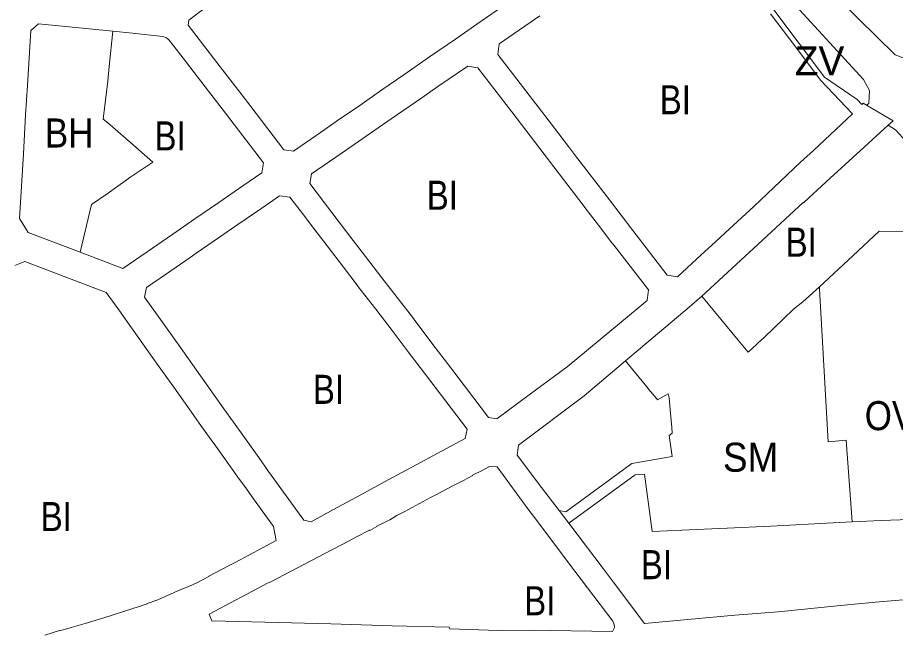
# Model space of a CAD drawing. Extents: x -650451 to -642268, y -1075216 to -1066610.
# Drawn here: x -646618.6 to -646255.8, y -1070923.2 to -1070669.1 of the extents above; entities that cross this region are included whole.
import ezdxf

# ---------------------------------------------------------------- set-up
doc = ezdxf.new("R2010")
doc.units = 0
doc.header["$LTSCALE"] = 4.8
for name, color, linetype, lineweight in [('1', 7, 'Continuous', 13), ('11', 7, 'Continuous', 13), ('15', 7, 'Continuous', 13), ('18', 7, 'Continuous', 13), ('2', 7, 'Continuous', 13), ('24', 7, 'Continuous', 13), ('40', 7, 'Continuous', 13)]:
    doc.layers.add(name, color=color, linetype=linetype, lineweight=lineweight)
doc.layers.add('62', color=7, linetype='Continuous')

msp = doc.modelspace()

# ---------------------------------------------------------------- linework, layer by layer
at = {"layer": '1'}
for points in [[(-646592.74, -1070766.01), (-646614.24, -1070757.93), (-646617.81, -1070752.22), (-646616.16, -1070725.38), (-646615.28, -1070709.36), (-646614.51, -1070697.27), (-646613.1, -1070674.47), (-646609.86, -1070671.71), (-646579.22, -1070674.79)], [(-646579.22, -1070674.79), (-646580.7, -1070689.38), (-646581.31, -1070695.46), (-646583.19, -1070711.07), (-646581.26, -1070712.65), (-646571.85, -1070720.76), (-646562.69, -1070728.82), (-646571.8, -1070734.95), (-646581.48, -1070741.91), (-646588, -1070746.38), (-646592.74, -1070766.01)]]:
    msp.add_lwpolyline(points, dxfattribs=at)
at = {"layer": '11'}
for points in [[(-646247.88, -1070687.56), (-646255.97, -1070684.58), (-646294.19, -1070646.82), (-646301.17, -1070639.92), (-646311.36, -1070629.16)], [(-646287.24, -1070780.35), (-646273.46, -1070767.61), (-646262.47, -1070757.43), (-646243.81, -1070757.55), (-646239.14, -1070757.8), (-646220.63, -1070758.81), (-646220.91, -1070795.61), (-646212.22, -1070805.08), (-646211.32, -1070874.4), (-646242.24, -1070875.39), (-646242.15, -1070876.28), (-646261.64, -1070876.91), (-646273.62, -1070877.57)], [(-646273.62, -1070877.57), (-646276.19, -1070843.8), (-646283.65, -1070844.41), (-646287.18, -1070781.33), (-646287.24, -1070780.35)]]:
    msp.add_lwpolyline(points, dxfattribs=at)
at = {"layer": '15'}
for points in [[(-646333.79, -1070624.42), (-646336.15, -1070622.85), (-646338.7, -1070622.45), (-646285.17, -1070693.77), (-646271.56, -1070702.94), (-646269.72, -1070705.08), (-646269.19, -1070704.55), (-646267.8, -1070705.35)], [(-646521.27, -1070649.9), (-646547.81, -1070670.15), (-646548.1, -1070672.21), (-646536.18, -1070687.66), (-646524.4, -1070703.04), (-646508.56, -1070723.74), (-646504.5, -1070724.28), (-646491.62, -1070715.45), (-646486.3, -1070711.74), (-646477.13, -1070705.41), (-646468, -1070699.01), (-646459.02, -1070692.78), (-646448.34, -1070685.41), (-646437.61, -1070678.02), (-646428.78, -1070671.9), (-646418.14, -1070664.55)], [(-646402.77, -1070668.45), (-646419.56, -1070680.05), (-646420.13, -1070684.38), (-646400.7, -1070709.54), (-646390.88, -1070722.36), (-646388.36, -1070725.66), (-646373.97, -1070744.49), (-646364.37, -1070757.12), (-646350.16, -1070775.6), (-646345.85, -1070776.25), (-646336.08, -1070767.24), (-646330.21, -1070761.82), (-646324.43, -1070756.49), (-646314.34, -1070747.19), (-646294.97, -1070728.93), (-646289.73, -1070724), (-646273.5, -1070708.86), (-646286.71, -1070695.05), (-646297.03, -1070681.4), (-646307.43, -1070667.64)], [(-646579.22, -1070674.79), (-646609.86, -1070671.71), (-646613.1, -1070674.47), (-646614.51, -1070697.27), (-646615.28, -1070709.36), (-646616.16, -1070725.38), (-646617.81, -1070752.22), (-646614.24, -1070757.93), (-646592.74, -1070766.01)], [(-646592.74, -1070766.01), (-646575.04, -1070772.84), (-646565.04, -1070765.98), (-646554.42, -1070758.64), (-646545.27, -1070752.32), (-646535.35, -1070745.54), (-646525.54, -1070738.72), (-646517.65, -1070733.33), (-646516.96, -1070729.11), (-646532.58, -1070708.64), (-646541.02, -1070697.81), (-646549.18, -1070687.18), (-646555.94, -1070678.43), (-646556.99, -1070677.45), (-646558.56, -1070676.91), (-646571.12, -1070675.62), (-646579.22, -1070674.79)], [(-646267.8, -1070705.35), (-646258.4, -1070710.8), (-646256.75, -1070711.76), (-646258.82, -1070713.65)], [(-646258.82, -1070713.65), (-646268.69, -1070722.68), (-646282.71, -1070735.5), (-646291.55, -1070743.61), (-646293.76, -1070745.64), (-646293.88, -1070745.53), (-646314.42, -1070764.61), (-646335.79, -1070784.31)], [(-646607.28, -1070924.28), (-646601.24, -1070922.45), (-646601.21, -1070922.55), (-646597.21, -1070921.5), (-646597.23, -1070921.42), (-646596.48, -1070921.2), (-646590.69, -1070919.54), (-646582.94, -1070917.19), (-646570.93, -1070913.38), (-646568.79, -1070912.59), (-646568.77, -1070912.65), (-646565.04, -1070911.35), (-646565.07, -1070911.27), (-646560.62, -1070909.67), (-646551.07, -1070905.53), (-646547.56, -1070904.07), (-646544.49, -1070902.67), (-646539.51, -1070900.14), (-646539.58, -1070899.99), (-646531.36, -1070895.72), (-646528.66, -1070894.25), (-646511.73, -1070885.17), (-646512.86, -1070879.39), (-646517.52, -1070872.91), (-646521.79, -1070866.98), (-646523.99, -1070863.92), (-646527.51, -1070859.02), (-646536.69, -1070846.22), (-646538.56, -1070843.6), (-646543.47, -1070836.73), (-646545.39, -1070834.04), (-646547.66, -1070830.82), (-646554.04, -1070821.8), (-646560.47, -1070812.84), (-646562.8, -1070809.59), (-646566.12, -1070804.92), (-646571.44, -1070797.41), (-646576.79, -1070789.95), (-646581.91, -1070782.8), (-646615.61, -1070769.98), (-646619.65, -1070771.61)], [(-646335.79, -1070784.31), (-646341.08, -1070788.84), (-646361.19, -1070805.8), (-646367.37, -1070811.01)], [(-646367.37, -1070811.01), (-646384.39, -1070825.4), (-646411.54, -1070845.82), (-646412.09, -1070850.01), (-646402.03, -1070863.32), (-646394.8, -1070872.88), (-646390.83, -1070878.08)], [(-646390.83, -1070878.08), (-646376.59, -1070896.75), (-646372.4, -1070902.33), (-646359.51, -1070919.54), (-646340.14, -1070917.72), (-646322.16, -1070916.14), (-646304.25, -1070914.63), (-646278.52, -1070912.13), (-646262.54, -1070910.59), (-646242.55, -1070908.96), (-646242.5, -1070912.81), (-646183.68, -1070907.2), (-646147.38, -1070905.61)]]:
    msp.add_lwpolyline(points, dxfattribs=at)
for points in [[(-646420.52, -1070835.01), (-646407.1, -1070825.05), (-646391.43, -1070813.52), (-646369.02, -1070794.9), (-646358.37, -1070786.01), (-646357.9, -1070781.68), (-646372.03, -1070763.39), (-646372.96, -1070762.19), (-646378.56, -1070754.88), (-646384.1, -1070747.66), (-646385.28, -1070746.12), (-646392.96, -1070736.08), (-646400.95, -1070725.63), (-646414.28, -1070708.14), (-646428.4, -1070689.86), (-646432.55, -1070689.24), (-646444.9, -1070697.64), (-646451.53, -1070702.27), (-646464.15, -1070710.94), (-646466.04, -1070712.24), (-646484.43, -1070725.08), (-646497.08, -1070733.65), (-646497.86, -1070737.68), (-646482.67, -1070757.72), (-646474.73, -1070767.91), (-646468.01, -1070776.68), (-646455.41, -1070792.92), (-646454.66, -1070793.88), (-646447.34, -1070803.67), (-646439.48, -1070813.93), (-646423.95, -1070834.45)], [(-646497.22, -1070877.56), (-646488.07, -1070872.46), (-646476.73, -1070866.39), (-646465.37, -1070860.15), (-646453.9, -1070853.97), (-646445.11, -1070849.23), (-646433.61, -1070843.06), (-646432.82, -1070839.18), (-646450.45, -1070816.03), (-646457.11, -1070807.28), (-646463.79, -1070798.5), (-646470.55, -1070789.67), (-646476.6, -1070781.92), (-646477.22, -1070781.13), (-646478.27, -1070779.74), (-646483.9, -1070772.33), (-646490.62, -1070763.47), (-646497.57, -1070754.46), (-646499.92, -1070751.4), (-646506.12, -1070743.36), (-646510.3, -1070742.84), (-646517.66, -1070747.84), (-646527.54, -1070754.62), (-646530.2, -1070756.46), (-646537.36, -1070761.39), (-646544.71, -1070766.53), (-646547.25, -1070768.31), (-646557.07, -1070775.09), (-646565.27, -1070780.67), (-646566.15, -1070784.66), (-646559.52, -1070793.94), (-646551.97, -1070804.52), (-646533.33, -1070830.75), (-646529.38, -1070836.27), (-646524.12, -1070843.61), (-646518.91, -1070850.95), (-646514.84, -1070856.69), (-646500.27, -1070876.87)], [(-646372.66, -1070922.87), (-646371.95, -1070921.1), (-646372, -1070919.88), (-646372.62, -1070918.59), (-646390.97, -1070894.38), (-646404.46, -1070876.47), (-646407.32, -1070872.68), (-646420.35, -1070854.79), (-646423.59, -1070854.62), (-646426.3, -1070856.12), (-646430.52, -1070858.22), (-646430.43, -1070858.37), (-646434.59, -1070860.54), (-646434.62, -1070860.5), (-646439.32, -1070862.86), (-646439.27, -1070862.95), (-646445.22, -1070866.14), (-646445.24, -1070866.09), (-646447.87, -1070867.49), (-646458.56, -1070873.21), (-646461.82, -1070874.95), (-646464.79, -1070876.65), (-646470.13, -1070879.34), (-646470.06, -1070879.48), (-646473.04, -1070881.08), (-646473.12, -1070880.93), (-646478.55, -1070883.72), (-646481.78, -1070885.45), (-646484.71, -1070886.98), (-646491.59, -1070890.64), (-646513.9, -1070902.3), (-646514.97, -1070902.75), (-646539.4, -1070915.68), (-646538.3, -1070918.46), (-646505.36, -1070919.27), (-646489.12, -1070919.72), (-646463.78, -1070920.43), (-646440.21, -1070921.07), (-646439.9, -1070921.7), (-646419.98, -1070922.36), (-646406.75, -1070922.27)]]:
    msp.add_lwpolyline(points, close=True, dxfattribs=at)
at = {"layer": '18'}
for points in [[(-646335.79, -1070784.31), (-646320.76, -1070802.46), (-646316.66, -1070807.4), (-646313.05, -1070804.07), (-646312.33, -1070803.39), (-646310.07, -1070801.3), (-646297.92, -1070789.63), (-646294.02, -1070786.62), (-646287.24, -1070780.35)], [(-646287.24, -1070780.35), (-646287.18, -1070781.33), (-646283.65, -1070844.41), (-646276.19, -1070843.8), (-646273.62, -1070877.57)], [(-646367.37, -1070811.01), (-646361.19, -1070805.8), (-646341.08, -1070788.84), (-646335.79, -1070784.31)], [(-646394.8, -1070872.88), (-646391.94, -1070873.33), (-646364.69, -1070853.45), (-646348.09, -1070850.57), (-646349.3, -1070841.85), (-646348.01, -1070840.87), (-646348.18, -1070838.52), (-646348.74, -1070832.73), (-646349.36, -1070826.25), (-646349.67, -1070824.67), (-646354.07, -1070827.06), (-646354.38, -1070826.7), (-646357.65, -1070822.88), (-646357.93, -1070822.48), (-646367.37, -1070811.01)], [(-646273.62, -1070877.57), (-646281.55, -1070877.98), (-646307.29, -1070879.32), (-646325.34, -1070880.17), (-646344.2, -1070881.01), (-646344.47, -1070881.02), (-646350.1, -1070881.27), (-646356.37, -1070881.56), (-646359.49, -1070857.84), (-646363.38, -1070858.06), (-646390.83, -1070878.08), (-646394.8, -1070872.88)]]:
    msp.add_lwpolyline(points, dxfattribs=at)
at = {"layer": '2'}
for points in [[(-646418.14, -1070664.55), (-646428.78, -1070671.9), (-646437.61, -1070678.02), (-646448.34, -1070685.41), (-646459.02, -1070692.78), (-646468, -1070699.01), (-646477.13, -1070705.41), (-646486.3, -1070711.74), (-646491.62, -1070715.45), (-646504.5, -1070724.28), (-646508.56, -1070723.74), (-646524.4, -1070703.04), (-646536.18, -1070687.66), (-646548.1, -1070672.21), (-646547.81, -1070670.15), (-646521.27, -1070649.9)], [(-646307.43, -1070667.64), (-646297.03, -1070681.4), (-646286.71, -1070695.05), (-646273.5, -1070708.86), (-646289.73, -1070724), (-646294.97, -1070728.93), (-646314.34, -1070747.19), (-646324.43, -1070756.49), (-646330.21, -1070761.82), (-646336.08, -1070767.24), (-646345.85, -1070776.25), (-646350.16, -1070775.6), (-646364.37, -1070757.12), (-646373.97, -1070744.49), (-646388.36, -1070725.66), (-646390.88, -1070722.36), (-646400.7, -1070709.54), (-646420.13, -1070684.38), (-646419.56, -1070680.05), (-646402.77, -1070668.45)], [(-646592.74, -1070766.01), (-646588, -1070746.38), (-646581.48, -1070741.91), (-646571.8, -1070734.95), (-646562.69, -1070728.82), (-646571.85, -1070720.76), (-646581.26, -1070712.65), (-646583.19, -1070711.07), (-646581.31, -1070695.46), (-646580.7, -1070689.38), (-646579.22, -1070674.79)], [(-646579.22, -1070674.79), (-646571.12, -1070675.62), (-646558.56, -1070676.91), (-646556.99, -1070677.45), (-646555.94, -1070678.43), (-646549.18, -1070687.18), (-646541.02, -1070697.81), (-646532.58, -1070708.64), (-646516.96, -1070729.11), (-646517.65, -1070733.33), (-646525.54, -1070738.72), (-646535.35, -1070745.54), (-646545.27, -1070752.32), (-646554.42, -1070758.64), (-646565.04, -1070765.98), (-646575.04, -1070772.84), (-646592.74, -1070766.01)], [(-646335.79, -1070784.31), (-646314.42, -1070764.61), (-646293.88, -1070745.53), (-646293.76, -1070745.64), (-646291.55, -1070743.61), (-646282.71, -1070735.5), (-646268.69, -1070722.68), (-646258.82, -1070713.65), (-646255.82, -1070715.54), (-646251.18, -1070720.48), (-646244.1, -1070726.79), (-646242.06, -1070728.61), (-646239.25, -1070731.88)], [(-646273.62, -1070877.57), (-646261.64, -1070876.91), (-646242.15, -1070876.28), (-646242.24, -1070875.39), (-646211.32, -1070874.4), (-646212.22, -1070805.08), (-646220.91, -1070795.61), (-646220.63, -1070758.81), (-646239.14, -1070757.8), (-646243.81, -1070757.55), (-646262.47, -1070757.43), (-646273.46, -1070767.61), (-646287.24, -1070780.35)], [(-646619.65, -1070771.61), (-646615.61, -1070769.98), (-646581.91, -1070782.8), (-646576.79, -1070789.95), (-646571.44, -1070797.41), (-646566.12, -1070804.92), (-646562.8, -1070809.59), (-646560.47, -1070812.84), (-646554.04, -1070821.8), (-646547.66, -1070830.82), (-646545.39, -1070834.04), (-646543.47, -1070836.73), (-646538.56, -1070843.6), (-646536.69, -1070846.22), (-646527.51, -1070859.02), (-646523.99, -1070863.92), (-646521.79, -1070866.98), (-646517.52, -1070872.91), (-646512.86, -1070879.39), (-646511.73, -1070885.17), (-646528.66, -1070894.25), (-646531.36, -1070895.72), (-646539.58, -1070899.99), (-646539.51, -1070900.14), (-646544.49, -1070902.67), (-646547.56, -1070904.07), (-646551.07, -1070905.53), (-646560.62, -1070909.67), (-646565.07, -1070911.27), (-646565.04, -1070911.35), (-646568.77, -1070912.65), (-646568.79, -1070912.59), (-646570.93, -1070913.38), (-646582.94, -1070917.19), (-646590.69, -1070919.54), (-646596.48, -1070921.2), (-646597.23, -1070921.42), (-646597.21, -1070921.5), (-646601.21, -1070922.55), (-646601.24, -1070922.45), (-646607.28, -1070924.28)], [(-646287.24, -1070780.35), (-646294.02, -1070786.62), (-646297.92, -1070789.63), (-646310.07, -1070801.3), (-646312.33, -1070803.39), (-646313.05, -1070804.07), (-646316.66, -1070807.4), (-646320.76, -1070802.46), (-646335.79, -1070784.31)], [(-646394.8, -1070872.88), (-646402.03, -1070863.32), (-646412.09, -1070850.01), (-646411.54, -1070845.82), (-646384.39, -1070825.4), (-646367.37, -1070811.01)], [(-646367.37, -1070811.01), (-646357.93, -1070822.48), (-646357.65, -1070822.88), (-646354.38, -1070826.7), (-646354.07, -1070827.06), (-646349.67, -1070824.67), (-646349.36, -1070826.25), (-646348.74, -1070832.73), (-646348.18, -1070838.52), (-646348.01, -1070840.87), (-646349.3, -1070841.85), (-646348.09, -1070850.57), (-646364.69, -1070853.45), (-646391.94, -1070873.33), (-646394.8, -1070872.88)], [(-646390.83, -1070878.08), (-646363.38, -1070858.06), (-646359.49, -1070857.84), (-646356.37, -1070881.56), (-646350.1, -1070881.27), (-646344.47, -1070881.02), (-646344.2, -1070881.01), (-646325.34, -1070880.17), (-646307.29, -1070879.32), (-646281.55, -1070877.98), (-646273.62, -1070877.57)], [(-646147.38, -1070905.61), (-646183.68, -1070907.2), (-646242.5, -1070912.81), (-646242.55, -1070908.96), (-646262.54, -1070910.59), (-646278.52, -1070912.13), (-646304.25, -1070914.63), (-646322.16, -1070916.14), (-646340.14, -1070917.72), (-646359.51, -1070919.54), (-646372.4, -1070902.33), (-646376.59, -1070896.75), (-646390.83, -1070878.08)]]:
    msp.add_lwpolyline(points, dxfattribs=at)
for points in [[(-646420.52, -1070835.01), (-646423.95, -1070834.45), (-646439.48, -1070813.93), (-646447.34, -1070803.67), (-646454.66, -1070793.88), (-646455.41, -1070792.92), (-646468.01, -1070776.68), (-646474.73, -1070767.91), (-646482.67, -1070757.72), (-646497.86, -1070737.68), (-646497.08, -1070733.65), (-646484.43, -1070725.08), (-646466.04, -1070712.24), (-646464.15, -1070710.94), (-646451.53, -1070702.27), (-646444.9, -1070697.64), (-646432.55, -1070689.24), (-646428.4, -1070689.86), (-646414.28, -1070708.14), (-646400.95, -1070725.63), (-646392.96, -1070736.08), (-646385.28, -1070746.12), (-646384.1, -1070747.66), (-646378.56, -1070754.88), (-646372.96, -1070762.19), (-646372.03, -1070763.39), (-646357.9, -1070781.68), (-646358.37, -1070786.01), (-646369.02, -1070794.9), (-646391.43, -1070813.52), (-646407.1, -1070825.05)], [(-646497.22, -1070877.56), (-646500.27, -1070876.87), (-646514.84, -1070856.69), (-646518.91, -1070850.95), (-646524.12, -1070843.61), (-646529.38, -1070836.27), (-646533.33, -1070830.75), (-646551.97, -1070804.52), (-646559.52, -1070793.94), (-646566.15, -1070784.66), (-646565.27, -1070780.67), (-646557.07, -1070775.09), (-646547.25, -1070768.31), (-646544.71, -1070766.53), (-646537.36, -1070761.39), (-646530.2, -1070756.46), (-646527.54, -1070754.62), (-646517.66, -1070747.84), (-646510.3, -1070742.84), (-646506.12, -1070743.36), (-646499.92, -1070751.4), (-646497.57, -1070754.46), (-646490.62, -1070763.47), (-646483.9, -1070772.33), (-646478.27, -1070779.74), (-646477.22, -1070781.13), (-646476.6, -1070781.92), (-646470.55, -1070789.67), (-646463.79, -1070798.5), (-646457.11, -1070807.28), (-646450.45, -1070816.03), (-646432.82, -1070839.18), (-646433.61, -1070843.06), (-646445.11, -1070849.23), (-646453.9, -1070853.97), (-646465.37, -1070860.15), (-646476.73, -1070866.39), (-646488.07, -1070872.46)], [(-646372.66, -1070922.87), (-646406.75, -1070922.27), (-646419.98, -1070922.36), (-646439.9, -1070921.7), (-646440.21, -1070921.07), (-646463.78, -1070920.43), (-646489.12, -1070919.72), (-646505.36, -1070919.27), (-646538.3, -1070918.46), (-646539.4, -1070915.68), (-646514.97, -1070902.75), (-646513.9, -1070902.3), (-646491.59, -1070890.64), (-646484.71, -1070886.98), (-646481.78, -1070885.45), (-646478.55, -1070883.72), (-646473.12, -1070880.93), (-646473.04, -1070881.08), (-646470.06, -1070879.48), (-646470.13, -1070879.34), (-646464.79, -1070876.65), (-646461.82, -1070874.95), (-646458.56, -1070873.21), (-646447.87, -1070867.49), (-646445.24, -1070866.09), (-646445.22, -1070866.14), (-646439.27, -1070862.95), (-646439.32, -1070862.86), (-646434.62, -1070860.5), (-646434.59, -1070860.54), (-646430.43, -1070858.37), (-646430.52, -1070858.22), (-646426.3, -1070856.12), (-646423.59, -1070854.62), (-646420.35, -1070854.79), (-646407.32, -1070872.68), (-646404.46, -1070876.47), (-646390.97, -1070894.38), (-646372.62, -1070918.59), (-646372, -1070919.88), (-646371.95, -1070921.1)]]:
    msp.add_lwpolyline(points, close=True, dxfattribs=at)
at = {"layer": '24'}
for points in [[(-646267.8, -1070705.35), (-646266.85, -1070704.65), (-646266.48, -1070699.34), (-646269.05, -1070694.79), (-646310.89, -1070648.97), (-646333.79, -1070624.42)], [(-646311.36, -1070629.16), (-646301.17, -1070639.92), (-646294.19, -1070646.82), (-646255.97, -1070684.58), (-646247.88, -1070687.56)], [(-646258.82, -1070713.65), (-646256.75, -1070711.76), (-646258.4, -1070710.8), (-646267.8, -1070705.35)], [(-646216.84, -1070759.26), (-646227.31, -1070745.82), (-646239.25, -1070731.88), (-646242.06, -1070728.61), (-646244.1, -1070726.79), (-646251.18, -1070720.48), (-646255.82, -1070715.54), (-646258.82, -1070713.65)]]:
    msp.add_lwpolyline(points, dxfattribs=at)
at = {"layer": '40'}
for points in [[(-646267.8, -1070705.35), (-646269.19, -1070704.55), (-646269.72, -1070705.08), (-646271.56, -1070702.94), (-646285.17, -1070693.77), (-646338.7, -1070622.45), (-646336.15, -1070622.85), (-646333.79, -1070624.42)], [(-646310.89, -1070648.97), (-646269.05, -1070694.79), (-646266.48, -1070699.34), (-646266.85, -1070704.65), (-646267.8, -1070705.35)]]:
    msp.add_lwpolyline(points, dxfattribs=at)

# ---------------------------------------------------------------- texts
at = {"layer": '62'}
msp.add_text('ZV', height=12, dxfattribs=at).set_placement((-646297.421, -1070693.026))
for s, width, p in [('BI', 0.85, (-646353.209, -1070709.117)), ('BH', 0.9, (-646607.283, -1070722.835)), ('BI', 0.85, (-646561.985, -1070724.041)), ('BI', 0.85, (-646449.496, -1070748.547)), ('BI', 0.85, (-646301.169, -1070767.97)), ('BI', 0.85, (-646496.531, -1070828.764)), ('OV.1', 0.9, (-646268.503, -1070839.626)), ('SM', 0.95, (-646327.081, -1070856.801)), ('BI', 0.85, (-646609.016, -1070881.317)), ('BI', 0.85, (-646360.993, -1070901.201)), ('BI', 0.85, (-646409.22, -1070916.136))]:
    msp.add_text(s, height=12, dxfattribs=dict(at, width=width)).set_placement(p)

doc.saveas('drawing.dxf')
